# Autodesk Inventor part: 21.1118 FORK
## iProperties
Created: 2007-04
Part Number: 21.1118 FORK
Document SubType Name: Modeling
Designer: Andy Moles
Material: Steel
Mass: 197.627 g
Surface Area: 147.043 cm^2
Volume: 25.1755 cm^3
Density: 7.85 g/cm^3
Author: Andy Moles
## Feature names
1. Base1
